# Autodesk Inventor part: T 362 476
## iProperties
Created: 2005-12
Part Number: T 362 476
Material: Durethan BKV 30 H
Document SubType Name: Modeling
Designer: I.Baliuc
Manufacturer: Standard
Standards Organization: Custom
Description: Vorkontaktanschlag
Density: 0.94 g/cm^3
Title: Vorkontaktanschlag
Company: Mayer & Müller AG Schaltgeräte
Author: T.Messerschmitt
Keywords: aus 362418
Revision Number: 362476
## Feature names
1. Extrusion_Ø16
2. Bohrung_Ø6.2 [Hole]
3. Extrusion3
4. Bezeichnung2 [Tagging]
